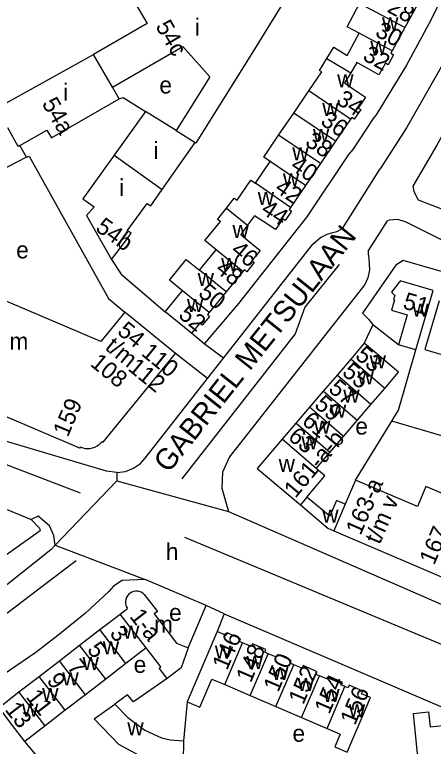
# Model space of a CAD drawing. Extents: x 161141 to 163125, y 381621 to 383200.
# Drawn here: x 162353 to 162451.8, y 382505.7 to 382678.5 of the extents above; entities that cross this region are included whole.
import ezdxf

# ---------------------------------------------------------------- set-up
doc = ezdxf.new("R2010")
doc.units = 0
for name, color, linetype in [('BLT_Basislijn', 7, 'Continuous'), ('BLT_Bebouwing', 7, 'Continuous'), ('BLT_Centroide', 7, 'Continuous'), ('BLT_Huisnummer', 7, 'Continuous'), ('BLT_Huisnummer_ tussenligend', 7, 'Continuous'), ('BLT_Huisnummer_reeks', 7, 'Continuous'), ('BLT_Onderverdeling_panden', 7, 'Continuous'), ('BLT_Straatnaam', 7, 'Continuous'), ('BLT_Vlakafsluiter', 7, 'Continuous')]:
    doc.layers.add(name, color=color, linetype=linetype)

msp = doc.modelspace()

# ---------------------------------------------------------------- linework, layer by layer
at = {"layer": 'BLT_Basislijn'}
for p, q in [((162430.4, 382628), (162439.3, 382642.09)), ((162436.49, 382622.66), (162441, 382629.8)), ((162435.11, 382608.02), (162436.71, 382606.42)), ((162437.52, 382605.24), (162435.54, 382600.9)), ((162436.71, 382606.42), (162437.52, 382605.24)), ((162443.62, 382600.54), (162437.52, 382605.24)), ((162397.78, 382600.76), (162394.74, 382603.26)), ((162402.32, 382597.41), (162397.78, 382600.76)), ((162398.54, 382592.58), (162391.01, 382598.45)), ((162398.54, 382592.58), (162402.32, 382597.41)), ((162479.27, 382571.4), (162442.04, 382582.52)), ((162338.06, 382577.23), (162368.49, 382565.55)), ((162393.09, 382555.06), (162469.44, 382523.2)), ((162393.96, 382528.95), (162398.21, 382538.98)), ((162402.46, 382536.94), (162400.8, 382532.78)), ((162389.01, 382521.69), (162381.04, 382516.21)), ((162365.73, 382494.5), (162355.42, 382506.85))]:
    msp.add_line(p, q, dxfattribs=at)
for points in [[(162481.15, 382756.28), (162474.21, 382733.16), (162467.06, 382712.43), (162459.94, 382695.21), (162451.23, 382677.24), (162445.49, 382666.61), (162438.37, 382654.83), (162437.62, 382653.96), (162432.82, 382646.7), (162431.81, 382645.52), (162421.95, 382630.76), (162405.82, 382610.3), (162397.78, 382600.76)], [(162463.91, 382687.17), (162456, 382670.16), (162445.53, 382651.82), (162439.3, 382642.09)], [(162470.04, 382681.38), (162463.13, 382666.53), (162452.65, 382647.68), (162447.01, 382638.04), (162447.24, 382636.72), (162448.24, 382634.8), (162461.07, 382629.85)], [(162377.66, 382658.62), (162378.61, 382658.94), (162383.92, 382655.66)], [(162355.84, 382644.86), (162356.47, 382645.13), (162375.17, 382611.5), (162379.03, 382608.25)], [(162377.15, 382570.34), (162374.71, 382570.72), (162341.47, 382580.52), (162303.7, 382596.26), (162245.74, 382621.4), (162216.51, 382633.67)], [(162458.92, 382622.76), (162447.96, 382628.25), (162445.41, 382629.52), (162443.46, 382630.14), (162441.41, 382629.99), (162441, 382629.8)], [(162402.32, 382597.41), (162423.39, 382624.3), (162425.19, 382625.87), (162426.75, 382626.65), (162428.08, 382627.07), (162429.06, 382627.32), (162430.4, 382628)], [(162436.49, 382622.66), (162436.45, 382622.02), (162436.61, 382620.9), (162436.77, 382618.22), (162436.37, 382616.36), (162435.7, 382614.8), (162403.75, 382574.08), (162402.1, 382570.48), (162401.91, 382566.7), (162403.46, 382561.19)], [(162375.9, 382620.71), (162378.18, 382617.24), (162388.55, 382608.33)], [(162455.13, 382617.45), (162454.54, 382617.62), (162444.74, 382620.48), (162442.96, 382619.35), (162435.11, 382608.02)], [(162429.58, 382619.51), (162421.54, 382609.43), (162419.25, 382603.14), (162392.5, 382568.9)], [(162442.04, 382582.52), (162443.63, 382585.12), (162447.74, 382599.34)], [(162377.15, 382570.34), (162379.17, 382570.62), (162381.05, 382571.4), (162382.75, 382572.51), (162383.78, 382573.75), (162398.54, 382592.58)], [(162433.49, 382568.57), (162442.04, 382582.52)], [(162345.42, 382563.14), (162351.37, 382561.53), (162356.87, 382559.29)], [(162362.6, 382553.21), (162362.25, 382555.45), (162361.22, 382557.73), (162358.55, 382560.04), (162356.87, 382559.29)], [(162403.46, 382561.19), (162479.51, 382527.99)], [(162356.87, 382559.29), (162358.91, 382557.25), (162359, 382556.62)], [(162359.01, 382556.56), (162337.09, 382541.02), (162328.81, 382535.56), (162314.16, 382527.02)], [(162359, 382556.62), (162359.01, 382556.56)], [(162362.6, 382553.21), (162361.54, 382552.11), (162350.35, 382543.18), (162342.61, 382537.88), (162332.63, 382530.95), (162322.85, 382524.63), (162313.17, 382519.51)], [(162343.16, 382531.08), (162361.67, 382545.16), (162367.53, 382549.6)], [(162383.83, 382545.11), (162378.38, 382544.88), (162376.37, 382543.54), (162375.25, 382542.27), (162369.73, 382537.16), (162363.18, 382531.84), (162358.04, 382527.86), (162345.48, 382519.35)], [(162398.21, 382538.98), (162383.83, 382545.11)], [(162402.46, 382536.94), (162398.21, 382538.98)], [(162402.46, 382536.94), (162459.1, 382512.7)], [(162381.04, 382516.21), (162379.64, 382517.86), (162376.64, 382515.63)], [(162393.72, 382516.22), (162392.85, 382506.99)]]:
    msp.add_lwpolyline(points, dxfattribs=at)
at = {"layer": 'BLT_Bebouwing'}
for p, q in [((162448.09, 382680.96), (162445.1, 382675.47)), ((162431.52, 382668.85), (162434.36, 382674.15)), ((162445.1, 382675.47), (162442.09, 382669.95)), ((162348.21, 382656.14), (162371.59, 382669.11)), ((162442.09, 382669.95), (162441.83, 382669.46)), ((162433.76, 382667.21), (162432.33, 382664.8)), ((162436.06, 382665.95), (162433.76, 382667.21)), ((162422.46, 382660.52), (162425.51, 382665.03)), ((162432.33, 382664.8), (162430.89, 382662.4)), ((162430.89, 382662.4), (162433.02, 382660.95)), ((162377.66, 382658.62), (162376.07, 382661.37)), ((162383.92, 382655.66), (162376.52, 382645.35)), ((162391.16, 382651.15), (162383.92, 382655.66)), ((162415.3, 382650.05), (162418.9, 382655.24)), ((162432.32, 382653.81), (162428.77, 382648.6)), ((162387.86, 382637.22), (162395.58, 382648.3)), ((162428.77, 382648.6), (162425.22, 382643.39)), ((162355.84, 382644.86), (162354.26, 382647.59)), ((162409.84, 382638.69), (162413.33, 382643.86)), ((162425.22, 382643.39), (162421.66, 382638.18)), ((162421.66, 382638.18), (162418.11, 382632.96)), ((162409.64, 382631.01), (162408, 382628.8)), ((162411.81, 382629.57), (162409.64, 382631.01)), ((162408, 382628.8), (162406.36, 382626.59)), ((162406.36, 382626.59), (162408.35, 382624.94)), ((162396.62, 382618.19), (162400.55, 382622.99)), ((162406.87, 382617.82), (162402.91, 382613.01)), ((162407.29, 382618.33), (162406.87, 382617.82)), ((162402.91, 382613.01), (162398.9, 382608.14)), ((162394.74, 382603.26), (162388.55, 382608.33)), ((162391.01, 382598.45), (162379.03, 382608.25)), ((162398.9, 382608.14), (162398.52, 382607.69)), ((162313.1, 382599.64), (162368.46, 382576.15)), ((162447.74, 382599.34), (162443.62, 382600.54)), ((162368.46, 382576.15), (162368.55, 382576.39)), ((162433.49, 382568.57), (162431.06, 382562.87)), ((162377.88, 382536.93), (162379.61, 382538.26)), ((162373.11, 382533.25), (162377.88, 382536.93)), ((162368.34, 382529.57), (162373.11, 382533.25)), ((162363.56, 382525.89), (162368.34, 382529.57)), ((162384.06, 382528.92), (162379.29, 382525.24)), ((162358.79, 382522.21), (162363.56, 382525.89)), ((162379.29, 382525.24), (162374.51, 382521.56)), ((162354.02, 382518.54), (162358.79, 382522.21)), ((162374.51, 382521.56), (162369.74, 382517.88)), ((162402.59, 382520.25), (162408.63, 382517.67)), ((162349.25, 382514.86), (162354.02, 382518.54)), ((162369.74, 382517.88), (162364.97, 382514.2)), ((162408.63, 382517.67), (162414.68, 382515.08)), ((162414.68, 382515.08), (162420.72, 382512.5)), ((162364.97, 382514.2), (162360.2, 382510.52)), ((162420.72, 382512.5), (162426.76, 382509.91)), ((162360.2, 382510.52), (162355.42, 382506.85)), ((162392.85, 382506.99), (162392.76, 382502.28))]:
    msp.add_line(p, q, dxfattribs=at)
for points in [[(162419.65, 382686.4), (162411.25, 382698.93), (162381.25, 382681.61), (162384.25, 382676.42), (162371.59, 382669.11)], [(162409.04, 382669.33), (162415.56, 382679.82), (162419.65, 382686.4)], [(162434.36, 382674.15), (162431.49, 382675.68), (162434.44, 382681.18)], [(162376.07, 382661.37), (162392.7, 382670.97), (162399.05, 382663.84)], [(162426.72, 382668.14), (162428.38, 382670.87), (162431.52, 382668.85)], [(162395.58, 382648.3), (162395.96, 382648.29), (162409.04, 382669.33)], [(162441.83, 382669.46), (162442.45, 382669.04), (162441.15, 382666.67), (162440.55, 382667.03), (162438.99, 382664.33), (162436.06, 382665.95)], [(162425.51, 382665.03), (162425, 382665.33), (162426.72, 382668.14)], [(162399.05, 382663.84), (162393.8, 382655.4), (162391.16, 382651.15)], [(162418.9, 382655.24), (162422.46, 382660.52)], [(162433.02, 382660.95), (162435.84, 382659.04), (162434.12, 382656.47), (162434.74, 382656.1), (162433.18, 382653.81), (162432.61, 382654.23), (162432.32, 382653.81)], [(162354.26, 382647.59), (162360.62, 382651.27), (162361.7, 382649.4), (162377.66, 382658.62)], [(162413.33, 382643.86), (162411.8, 382644.86), (162415.3, 382650.05)], [(162355.84, 382644.86), (162351.39, 382642.58), (162334.16, 382633.75)], [(162376.52, 382645.35), (162369.13, 382635.04), (162371.74, 382633.14)], [(162405.5, 382634.68), (162408.72, 382639.45), (162409.84, 382638.69)], [(162379.59, 382627.48), (162384.29, 382633.89), (162385.16, 382633.35), (162387.86, 382637.22)], [(162402.98, 382632.83), (162404.82, 382635.18), (162405.5, 382634.68)], [(162371.74, 382633.14), (162369.97, 382631.07), (162375.9, 382620.71)], [(162401.57, 382629.65), (162400.9, 382630.17), (162402.98, 382632.83)], [(162418.11, 382632.96), (162417.81, 382632.52), (162418.36, 382632.11), (162416.87, 382629.92), (162416.32, 382630.32), (162414.55, 382627.76), (162411.81, 382629.57)], [(162400.55, 382622.99), (162397.9, 382625.17), (162401.57, 382629.65)], [(162375.9, 382620.71), (162378.9, 382624.7), (162380.55, 382626.89), (162379.59, 382627.48)], [(162408.35, 382624.94), (162410.93, 382622.79), (162408.99, 382620.43), (162409.53, 382619.98), (162407.85, 382617.8), (162407.29, 382618.33)], [(162379.03, 382608.25), (162375.86, 382604.38), (162373.38, 382601.34), (162328, 382620.59)], [(162392.61, 382613.29), (162389.52, 382615.83), (162393.52, 382620.72), (162396.62, 382618.19)], [(162447.74, 382599.34), (162451.79, 382613.38), (162443.98, 382615.64), (162443.87, 382615.28), (162443.75, 382615.31), (162441.99, 382612.96), (162442.72, 382612.2), (162442.45, 382611.24), (162442.65, 382611.18), (162441.94, 382608.72), (162445.67, 382607.65), (162443.62, 382600.54)], [(162388.55, 382608.33), (162391.71, 382612.2), (162392.61, 382613.29)], [(162453.2, 382610.91), (162449.81, 382599.42), (162456.18, 382597.54)], [(162398.52, 382607.69), (162399.02, 382607.22), (162397.3, 382605.18), (162396.74, 382605.65), (162394.74, 382603.26)], [(162435.54, 382600.9), (162432.33, 382597.16)], [(162443.6, 382594.03), (162435.54, 382600.9)], [(162373.66, 382577.68), (162373.9, 382577.52), (162391.01, 382598.45)], [(162432.33, 382597.16), (162429.1, 382593.38)], [(162429.1, 382593.38), (162425.86, 382589.6)], [(162440.36, 382590.23), (162443.6, 382594.03)], [(162425.86, 382589.6), (162422.63, 382585.82)], [(162437.12, 382586.46), (162440.36, 382590.23)], [(162422.63, 382585.82), (162419.39, 382582.04)], [(162433.89, 382582.68), (162437.12, 382586.46)], [(162430.65, 382578.9), (162433.89, 382582.68)], [(162419.39, 382582.04), (162416.15, 382578.26)], [(162427.42, 382575.12), (162430.65, 382578.9)], [(162368.55, 382576.39), (162369.1, 382576.19), (162369.67, 382576.07), (162370.25, 382576.02), (162370.84, 382576.06), (162371.41, 382576.17), (162371.96, 382576.37), (162372.48, 382576.63), (162372.96, 382576.97), (162373.39, 382577.36), (162373.66, 382577.68)], [(162416.15, 382578.26), (162410.24, 382571.35)], [(162424.18, 382571.34), (162427.42, 382575.12)], [(162410.24, 382571.35), (162420.45, 382562.7)], [(162422.01, 382564.56), (162426.21, 382569.6), (162424.18, 382571.34)], [(162468.97, 382555.27), (162466.36, 382556.39), (162465.68, 382554.77), (162455.89, 382558.94), (162457.94, 382563.75), (162450.1, 382567.09), (162448.08, 382562.36), (162433.49, 382568.57)], [(162431.06, 382562.87), (162428.95, 382563.76), (162427.38, 382560.07), (162422.01, 382564.56)], [(162420.45, 382562.7), (162426.95, 382557.19), (162428.38, 382556.58)], [(162428.38, 382556.58), (162459.28, 382543.39), (162460, 382544.99), (162463.86, 382543.34)], [(162383.6, 382541.55), (162383.25, 382541.85), (162382.86, 382542.08), (162382.43, 382542.24), (162381.99, 382542.32), (162381.53, 382542.32), (162381.08, 382542.24), (162380.65, 382542.09), (162380.26, 382541.86), (162379.91, 382541.57), (162379.62, 382541.22), (162379.39, 382540.82), (162379.24, 382540.4), (162379.16, 382539.95), (162379.17, 382539.49), (162379.25, 382539.04), (162379.41, 382538.62), (162379.61, 382538.26)], [(162383.6, 382541.55), (162386.7, 382537.53), (162385.94, 382536.94), (162391.23, 382530.08), (162393.96, 382528.95)], [(162400.8, 382532.78), (162393.72, 382516.22)], [(162406.82, 382530.15), (162406.07, 382530.47), (162406.35, 382531.11), (162403.17, 382532.47), (162402.91, 382531.88), (162400.8, 382532.78)], [(162389.01, 382521.69), (162387.1, 382524.17), (162387.48, 382524.47), (162384.06, 382528.92)], [(162393.96, 382528.95), (162392.29, 382524.22), (162389.01, 382521.69)], [(162412.86, 382527.56), (162412.06, 382527.9), (162412.33, 382528.53), (162409.12, 382529.9), (162408.86, 382529.28), (162406.82, 382530.15)], [(162418.9, 382524.95), (162418.01, 382525.33), (162418.29, 382525.98), (162415.1, 382527.35), (162414.83, 382526.72), (162412.86, 382527.56)], [(162424.94, 382522.36), (162424.01, 382522.76), (162424.28, 382523.39), (162421.12, 382524.74), (162420.85, 382524.11), (162418.9, 382524.95)], [(162430.98, 382519.78), (162430, 382520.19), (162430.29, 382520.86), (162427.11, 382522.22), (162426.83, 382521.55), (162424.94, 382522.36)], [(162393.72, 382516.22), (162396.71, 382514.94), (162399.55, 382521.55), (162402.59, 382520.25)], [(162431.53, 382504.34), (162435.06, 382512.6), (162437.03, 382517.19), (162434.9, 382518.1), (162435.17, 382518.74), (162431.98, 382520.11), (162431.71, 382519.46), (162430.98, 382519.78)], [(162382.4, 382503.53), (162377.58, 382506.11), (162371.77, 382512.16), (162376.64, 382515.63)], [(162376.64, 382515.63), (162379.7, 382512.46), (162383.75, 382509.46), (162387.68, 382507.7), (162389.74, 382507.23), (162392.85, 382506.99)], [(162355.42, 382506.85), (162352.3, 382510.9), (162349.25, 382514.86)], [(162448.06, 382503.87), (162447.12, 382513.46), (162450.72, 382513.83), (162451.1, 382510.26), (162457.05, 382510.88), (162457.66, 382504.78)], [(162426.76, 382509.91), (162429.88, 382508.58), (162428.6, 382505.6), (162431.53, 382504.34)]]:
    msp.add_lwpolyline(points, dxfattribs=at)
at = {"layer": 'BLT_Onderverdeling_panden'}
for p, q in [((162445.1, 382675.47), (162434.44, 382681.18)), ((162442.09, 382669.95), (162434.36, 382674.15)), ((162426.72, 382668.14), (162432.33, 382664.8)), ((162432.32, 382653.81), (162422.46, 382660.52)), ((162428.77, 382648.6), (162418.9, 382655.24)), ((162391.16, 382651.15), (162395.58, 382648.3)), ((162425.22, 382643.39), (162415.3, 382650.05)), ((162376.52, 382645.35), (162387.86, 382637.22)), ((162421.66, 382638.18), (162413.33, 382643.86)), ((162418.11, 382632.96), (162409.84, 382638.69)), ((162402.98, 382632.83), (162408, 382628.8)), ((162406.87, 382617.82), (162400.55, 382622.99)), ((162402.91, 382613.01), (162396.62, 382618.19)), ((162398.9, 382608.14), (162392.61, 382613.29)), ((162422.01, 382564.56), (162420.45, 382562.7)), ((162431.06, 382562.87), (162428.38, 382556.58)), ((162384.06, 382528.92), (162377.88, 382536.93)), ((162379.29, 382525.24), (162373.11, 382533.25)), ((162374.51, 382521.56), (162368.34, 382529.57)), ((162402.59, 382520.25), (162406.82, 382530.15)), ((162408.63, 382517.67), (162412.86, 382527.56)), ((162369.74, 382517.88), (162363.56, 382525.89)), ((162414.68, 382515.08), (162418.9, 382524.95)), ((162364.97, 382514.2), (162358.79, 382522.21)), ((162420.72, 382512.5), (162424.94, 382522.36)), ((162360.2, 382510.52), (162354.02, 382518.54)), ((162426.76, 382509.91), (162430.98, 382519.78))]:
    msp.add_line(p, q, dxfattribs=at)
for points in [[(162376.07, 382661.37), (162371.59, 382669.11)], [(162354.26, 382647.59), (162353.87, 382647.37), (162351.4, 382651.76)], [(162440.36, 382590.23), (162432.33, 382597.16)], [(162437.12, 382586.46), (162429.1, 382593.38)], [(162433.89, 382582.68), (162425.86, 382589.6)], [(162430.65, 382578.9), (162422.63, 382585.82)], [(162427.42, 382575.12), (162419.39, 382582.04)], [(162424.18, 382571.34), (162416.15, 382578.26)]]:
    msp.add_lwpolyline(points, dxfattribs=at)
at = {"layer": 'BLT_Vlakafsluiter'}
for p, q in [((162377.15, 382570.34), (162377.16, 382568.4)), ((162377.16, 382568.4), (162362.6, 382553.21)), ((162377.16, 382568.4), (162403.46, 382561.19))]:
    msp.add_line(p, q, dxfattribs=at)
msp.add_lwpolyline([(162362.6, 382553.21), (162383.83, 382545.11)], dxfattribs=at)

# ---------------------------------------------------------------- texts
at = {"layer": 'BLT_Centroide'}
for s, p in [('i', (162395.54, 382673.59)), ('w', (162439.73, 382674.81)), ('w', (162436.95, 382669.25)), ('w', (162429.14, 382661.33)), ('i', (162364.44, 382658.22)), ('e', (162387.17, 382659.9)), ('w', (162425.62, 382654.56)), ('w', (162423.41, 382648.44)), ('i', (162385.79, 382644.44)), ('w', (162418.54, 382644.12)), ('i', (162377.67, 382635.69)), ('w', (162416.33, 382638)), ('w', (162410.38, 382633.59)), ('w', (162404.42, 382625.77)), ('e', (162353.37, 382620.95)), ('w', (162401.75, 382618)), ('w', (162396.2, 382614.44)), ('w', (162393.67, 382608.28)), ('w', (162446.86, 382607.2)), ('m', (162351.78, 382599.38)), ('w', (162436.79, 382594.97)), ('w', (162433.93, 382591.16)), ('w', (162430.57, 382586.85)), ('w', (162427.41, 382583.29)), ('w', (162423.69, 382579.51)), ('e', (162433.42, 382579.32)), ('w', (162420.69, 382575.81)), ('w', (162415.32, 382570.52)), ('w', (162425.59, 382558.5)), ('h', (162388.69, 382549.67)), ('e', (162389.47, 382535.3)), ('w', (162378.58, 382531.08)), ('m', (162385.92, 382532.52)), ('w', (162373.81, 382527.41)), ('w', (162400.27, 382526.39)), ('w', (162369.03, 382523.72)), ('e', (162381.11, 382523.03)), ('w', (162407.73, 382523.91)), ('w', (162413.77, 382521.31)), ('w', (162364.27, 382520.05)), ('w', (162419.81, 382518.72)), ('w', (162359.5, 382516.38)), ('w', (162425.84, 382516.14)), ('w', (162354.72, 382512.69)), ('w', (162431.89, 382512.55)), ('w', (162379.6, 382508.28)), ('e', (162418.59, 382506.76))]:
    msp.add_text(s, height=4, dxfattribs=at).set_placement(p)
at = {"layer": 'BLT_Huisnummer'}
for s, rotation, p in [('54c', 300.0128, (162386.16, 382675.79)), ('32', 331.1661, (162434.92, 382667.97)), ('34', 325.7658, (162428.64, 382657.71)), ('54a', 299.9868, (162359.33, 382657.55)), ('38', 325.7701, (162421.31, 382647.85)), ('42', 325.7689, (162414.16, 382636.89)), ('44', 326.5067, (162410.9, 382631.77)), ('54b', 324.2448, (162371.86, 382627.65)), ('46', 320.5078, (162403.8, 382622.4)), ('51', 343.8904, (162444.42, 382609.19)), ('52', 320.6914, (162391.44, 382607.19)), ('53', 320.1183, (162433.14, 382597.56)), ('57', 320.1183, (162426.84, 382589.73)), ('63', 320.1183, (162417.3, 382578.39)), ('146', 66.8413, (162403.14, 382523.46)), ('5', 307.6311, (162369.95, 382528.46)), ('150', 66.8421, (162415.22, 382518.28)), ('9', 307.6276, (162360.42, 382521.18)), ('154', 66.8407, (162427.26, 382513.09)), ('156', 66.829, (162433.33, 382510.46)), ('13', 307.6177, (162350.56, 382514.32))]:
    msp.add_text(s, height=4, rotation=rotation, dxfattribs=at).set_placement(p)
at = {"layer": 'BLT_Huisnummer_ tussenligend'}
for s, rotation, p in [('28', 331.4529, (162440.71, 382679.29)), ('30', 331.454, (162437.85, 382673.62)), ('36', 325.7658, (162424.98, 382652.77)), ('40', 325.7701, (162417.83, 382642.18)), ('48', 320.5078, (162400.15, 382618)), ('50', 320.5078, (162396.12, 382612.33)), ('55', 320.1183, (162430.07, 382593.66)), ('59', 320.1183, (162423.52, 382585.98)), ('61', 320.1183, (162420.57, 382582.06)), ('3', 307.6321, (162375.26, 382532.31)), ('148', 66.8413, (162408.75, 382520.51)), ('7', 307.6311, (162365.22, 382524.34)), ('152', 66.8421, (162421.13, 382515.34)), ('11', 307.6276, (162355.52, 382517.29))]:
    msp.add_text(s, height=4, rotation=rotation, dxfattribs=at).set_placement(p)
at = {"layer": 'BLT_Huisnummer_reeks'}
for s, rotation, p in [('54', 320.7314, (162377.01, 382603.3)), ('t/m', 320.7314, (162374.11, 382599.62)), ('110', 320.7314, (162382.66, 382598.24)), ('108', 320.7314, (162370.61, 382595.77)), ('112', 320.7314, (162379.53, 382594.68)), ('159', 66.9684, (162365.56, 382578.56)), ('161-a-b', 50.1183, (162419.28, 382564.12)), ('163-a', 66.6137, (162434.65, 382555.35)), ('t/m v', 66.6137, (162439.16, 382553.19)), ('167-a', 66.9271, (162452.03, 382548.32)), ('1-a', 307.6321, (162379.98, 382536.33))]:
    msp.add_text(s, height=4, rotation=rotation, dxfattribs=at).set_placement(p)
at = {"layer": 'BLT_Straatnaam'}
msp.add_text('GABRIEL METSULAAN', height=5, rotation=51.5084, dxfattribs=at).set_placement((162389.32, 382570.04))

doc.saveas('drawing.dxf')
